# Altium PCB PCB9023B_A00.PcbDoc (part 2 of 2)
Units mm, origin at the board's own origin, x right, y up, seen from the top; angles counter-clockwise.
Board outline 30 x 45 mm, 4 copper layers (Top Layer, Signal Layer 2, Signal Layer 3, Bottom Layer), stack 1.606 mm thick; 75 components, 84 nets, 313 pads, 395 vias.
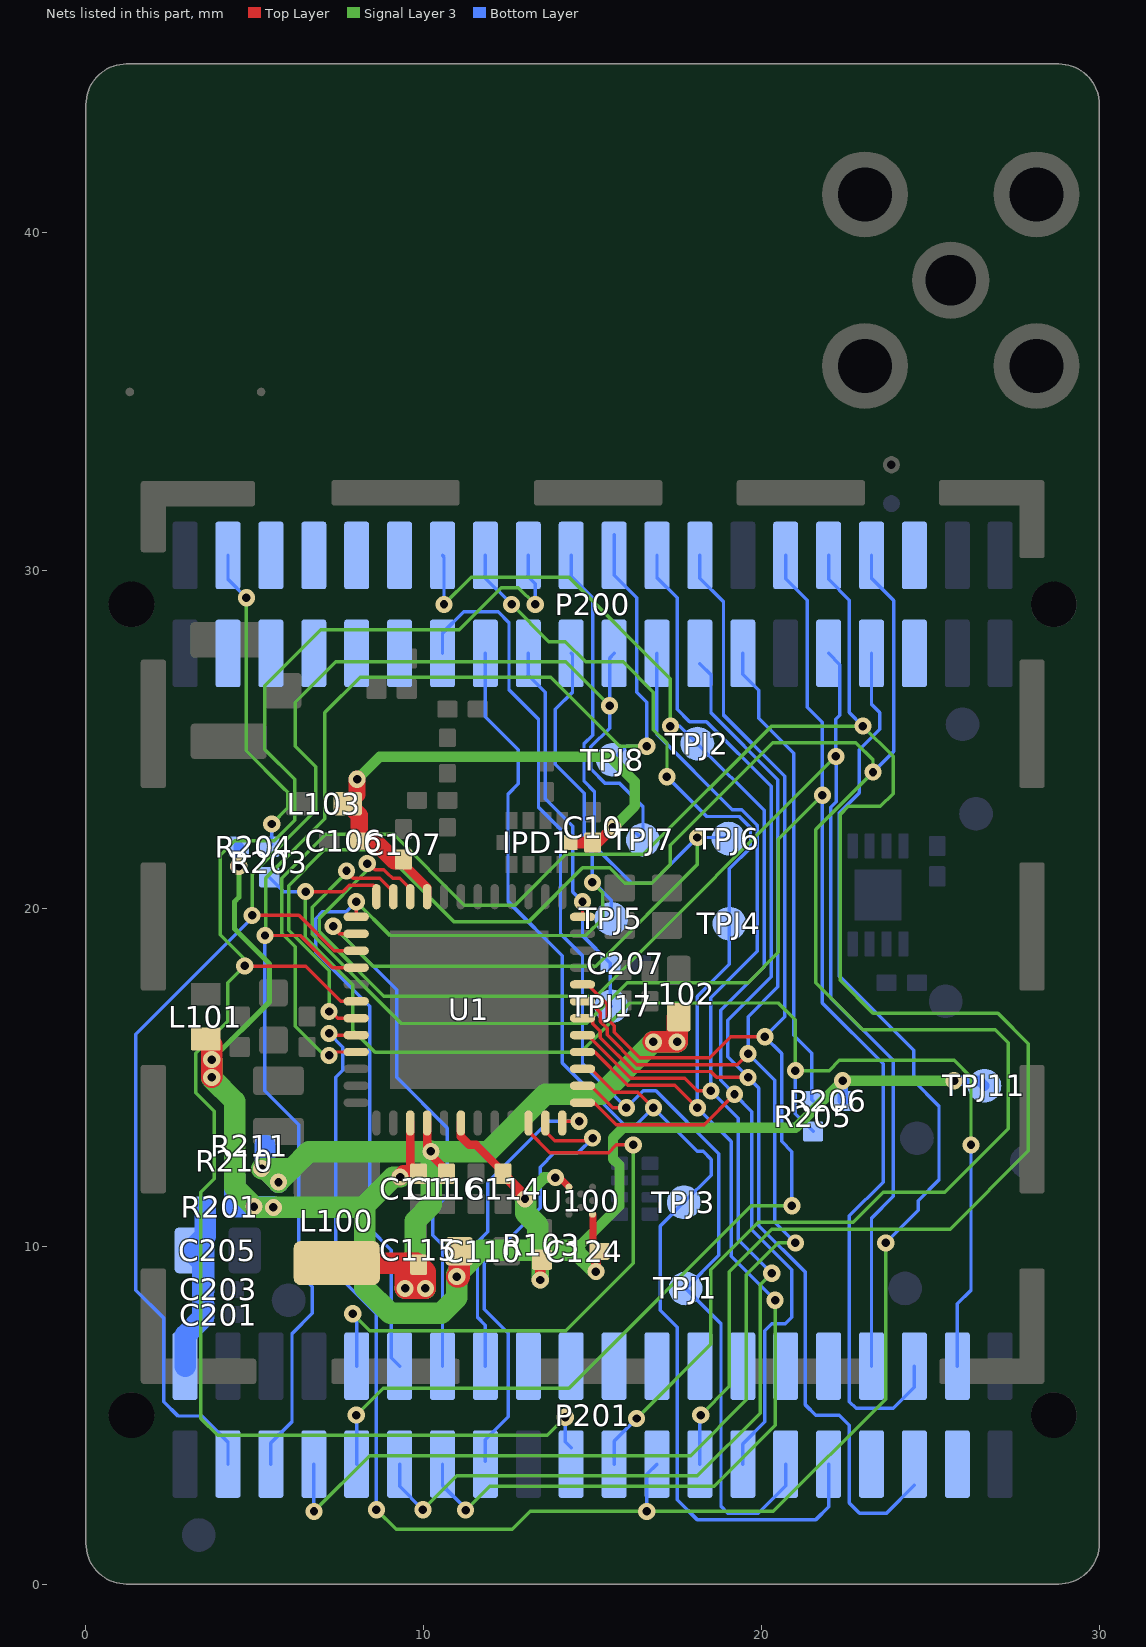
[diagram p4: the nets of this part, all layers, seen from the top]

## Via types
v1: diameter 0.508, hole 0.25, Top Layer to Bottom Layer, tented both sides, 364 vias
v2: diameter 0.5, hole 0.25, Top Layer to Bottom Layer, tented both sides, 31 vias

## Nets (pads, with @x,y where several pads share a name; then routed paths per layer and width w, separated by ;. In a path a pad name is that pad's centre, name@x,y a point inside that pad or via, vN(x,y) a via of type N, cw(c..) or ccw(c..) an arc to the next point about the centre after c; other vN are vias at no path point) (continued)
RADIO_#RESET: C207.1 P200.17 TPJ17.1 U1.12 | length 11.9
  Top Layer w0.102: U1.12@14.7,19.75 v1(14.7,20.2)
  Bottom Layer w0.102: P200.17@13.095,27.55 13.095,26.905 13.6,26.4 13.6,23.246 14.413,22.433 14.413,20.487 v1(14.7,20.2) 14.7,19.2 C207.1@15.525,18.375 15.525,17.125 TPJ17.1@15.55,17.1
RADIO_PA0: P200.19 P201.12 TPJ5.1 U1.25 | length 34
  Top Layer w0.102: U1.25@8,19.75 v1(8,20.2)
  Signal Layer 3 w0.102: v1(8,20.2) 9,19.2 14.8,19.2 15.3,19.7 15.3,20.464 v1(14.994,20.77)
  Bottom Layer w0.102: v1(8,20.2) 7.7,19.9 7,19.9 6.8,19.7 6.8,18.7 8.4,17.1 8.4,10.525 9.042,9.884 9.042,6.693 P201.12@9.285,6.45 ; P200.19@14.365,27.55 14.403,27.512 14.403,26.403 13.894,25.894 13.894,24.271 14.75,23.414 14.75,21.863 14.994,21.618 v1(14.994,20.77) 15.025,20.77 15.55,20.244 TPJ5.1@15.55,19.7
RADIO_PA1: P200.20 P201.14 TPJ6.1 U1.26 | length 42.9
  Top Layer w0.102: v1(7.32,19.472) 7.32,19.428 7.498,19.25 U1.26@8,19.25
  Signal Layer 3 w0.102: v1(7.32,19.472) 8.498,18.294 15.094,18.294 18.1,21.3 v1(18.1,22.1)
  Bottom Layer w0.102: v1(7.32,19.472) 9.2,17.592 9.2,15 10.7,13.5 10.7,11.5 10.269,11.069 10.269,10.331 10.555,10.045 P201.14@10.555,6.45 ; P200.20@14.365,30.45 14.365,29.835 15,29.2 15,25.125 14.744,24.87 14.744,23.769 ; 14.745,23.769 15.055,23.459 15.055,21.845 16.155,20.745 16.745,20.745 v1(18.1,22.1) 18.99,22.1 TPJ6.1@19.02,22.07
RADIO_PA2: P200.21 P201.3 TPJ7.1 U1.27 | length 47.4
  Top Layer w0.102: v1(4.919,19.794) 6.306,19.794 7.35,18.75 U1.27@8,18.75
  Signal Layer 3 w0.102: v1(4.919,19.794) 4.919,21.019 6.803,22.903 6.803,24.197 6.2,24.8 6.2,26.1 7.4,27.3 14.2,27.3 v1(15.5,26)
  Bottom Layer w0.102: P201.3@4.205,3.55 4.205,4.195 3.425,4.975 2.725,4.975 2.3,5.4 2.3,7.875 1.475,8.7 1.475,16.275 4.919,19.719 v1(4.919,19.794) ; P200.21@15.635,27.55 15.5,27.415 v1(15.5,26) 15.5,25.338 14.948,24.785 14.948,24.13 15.377,23.7 15.8,23.7 16.49,23.01 TPJ7.1@16.49,22.03 TPJ7.1@16.252,22.268
RADIO_PA3: P200.22 P201.5 TPJ8.1 U1.28 | length 45.8
  Top Layer w0.102: v1(5.3,19.2) 6.348,19.2 7.298,18.25 U1.28@8,18.25
  Signal Layer 3 w0.102: v1(5.3,19.2) 5.325,19.225 5.325,20.9 7.075,22.65 7.075,25.8 8.122,26.847 13.753,26.847 15.8,24.8 v1(16.6,24.8)
  Bottom Layer w0.102: v1(5.3,19.2) 5.294,19.194 5.294,14.606 6.3,13.6 6.3,9.2 6.7,8.8 6.7,8.016 6.1,7.416 6.1,4.8 5.475,4.175 P201.5@5.475,3.55 ; TPJ8.1@15.6,24.4 16,24.8 v1(16.6,24.8) 16.6,26.1 16.3,26.4 16.3,29.2 15.635,29.865 P200.22@15.635,30.45 P200.22@15.635,31.065
RADIO_PA5: P200.18 P201.19 U1.30 | length 51.8
  Top Layer w0.102: v1(4.7,18.3) 4.706,18.294 6.504,18.294 7.548,17.25 U1.30@8,17.25
  Signal Layer 3 w0.102: v1(13.3,29) 12.8,29.5 12.3,29.5 11.048,28.248 6.948,28.248 5.294,26.594 5.294,24.706 6.181,23.819 6.181,22.606 5.575,22 4.4,22 3.973,21.573 3.973,19.227 4.7,18.5 v1(4.7,18.3) 4.2,17.8 4.2,16.665 3.255,15.72 3.255,14.545 3.8,14 3.8,12 3.4,11.6 3.4,4.9 3.9,4.4 13.65,4.4 v1(14.188,4.938)
  Bottom Layer w0.102: P200.18@13.095,30.45 13.095,29.822 13.3,29.617 v1(13.3,29) ; v1(14.188,4.938) 14.188,4.215 P201.19@14.365,4.038
RADIO_PB11: P200.34 P201.21 U1.31 | length 67.5
  Top Layer w0.102: v1(7.198,16.95) 7.248,16.95 7.448,16.75 U1.31@8,16.75
  Signal Layer 3 w0.102: v1(7.198,16.95) 7.198,18.157 6,19.355 6,20.676 7.059,21.735 8.765,21.735 10.9,19.6 13.1,19.6 14.7,21.2 15.5,21.2 15.956,20.744 16.744,20.744 17.3,21.3 17.3,21.875 20.332,24.907 22.793,24.907 23.3,24.4 v1(23.3,24.037) 21.6,22.337 21.6,17.8 22.994,16.406 26.918,16.406 27.3,16.025 27.3,13.475 25.422,11.597 23.597,11.597 22.71,10.71 19.9,10.71 18.5,9.31 18.5,7.1 v1(16.3,4.9)
  Bottom Layer w0.102: P201.21@15.635,3.55 15.635,4.235 v1(16.3,4.9) ; P200.34@23.255,30.45 23.255,29.771 23.91,29.116 23.91,24.647 v1(23.3,24.037)
RADIO_PB12: P200.33 P201.23 U1.32 | length 58.7
  Top Layer w0.102: v1(7.198,16.3) 7.248,16.25 U1.32@8,16.25
  Signal Layer 3 w0.102: v1(8.6,2.2) 9.183,1.617 12.617,1.617 13.15,2.15 v1(16.6,2.15) 20.35,2.15 23.675,5.475 v1(23.675,10.1)
  Bottom Layer w0.102: v1(7.198,16.3) 7.604,15.894 7.604,15.204 7.4,15 7.4,9.2 8.6,8 v1(8.6,2.2) ; v1(16.6,2.15) 16.6,3.245 P201.23@16.905,3.55 ; P200.33@23.255,27.55 23.255,26.045 23.5,25.8 23.5,25.3 22.894,24.694 22.894,23.418 22.294,22.818 22.294,18.006 24.5,15.8 24.5,14.9 25.252,14.148 25.252,11.965 24.64,11.353 24.64,11.066 v1(23.675,10.1)
RADIO_PB13: P200.32 P201.25 U1.33 | length 68.2
  Top Layer w0.102: v1(7.198,15.65) 7.198,15.7 7.148,15.75 U1.33@8,15.75
  Signal Layer 3 w0.102: v1(7.198,15.65) 7.05,15.65 6.193,16.507 6.193,17.568 6.2,17.575 6.2,18.867 5.796,19.27 5.796,20.89 7.1,22.193 9.107,22.193 11.2,20.1 12.7,20.1 14.2,21.6 16.5,21.6 20.3,25.4 v1(23,25.4) 23.9,24.5 23.9,23.4 23.519,23.019 22.57,23.019 22.332,22.781 22.332,17.868 23.3,16.9 27,16.9 27.9,16 27.9,12.825 25.581,10.506 20.306,10.506 19.05,9.25 19.05,5.85 v1(18.2,5)
  Bottom Layer w0.102: P201.25@18.175,3.55 18.175,4.975 v1(18.2,5) ; P200.32@21.985,30.45 21.985,29.741 22.6,29.126 22.6,25.8 v1(23,25.4)
RADIO_PC9: P201.10 U1.46 | length 18.1
  Top Layer w0.102: U1.46@13.1,13.65 13.1,13.4 13.729,12.771 15.471,12.771 15.7,13 v1(16.2,13)
  Signal Layer 3 w0.102: v1(7.9,8) 8.4,7.5 14.2,7.5 16.2,9.5 v1(16.2,13)
  Bottom Layer w0.102: v1(7.9,8) 8.015,7.885 P201.10@8.015,6.45
RADIO_PC10: P201.15 U1.47 | length 13.7
  Top Layer w0.102: U1.47@13.6,13.65 13.6,13.4 13.877,13.123 14.923,13.123 v1(15,13.2)
  Bottom Layer w0.102: P201.15@11.825,3.635 11.825,4.275 12.5,4.95 12.5,7.425 11.794,8.131 11.794,9.494 13.444,11.144 13.444,12.344 13.866,12.766 14.566,12.766 v1(15,13.2)
RADIO_PC11: P201.16 U1.48 | length 9.6
  Top Layer w0.102: U1.48@14.098,13.65 U1.48@14.1,13.65 14.15,13.7 v1(14.6,13.7)
  Bottom Layer w0.102: P201.16@11.825,6.45 11.825,7.665 11.59,7.9 11.59,10.115 11.9,10.425 11.9,11.9 13.7,13.7 v1(14.6,13.7)
RADIO_PD13: P200.31 P201.34 U1.22 | length 45.8
  Top Layer w0.102: v1(8.325,21.328) 8.37,21.328 8.557,21.142 8.821,21.142 8.919,21.043 8.925,21.043 9.079,20.89 9.286,20.89 9.598,20.578 U1.22@9.598,20.35
  Signal Layer 3 w0.102: v1(8.325,21.328) 8.325,21.125 6.913,19.713 6.913,19.304 8.811,17.406 15.106,17.406 v1(22.2,24.5)
  Bottom Layer w0.102: P200.31@21.985,27.55 22.319,27.216 22.319,25.725 22.2,25.606 v1(22.2,24.5) 22.2,24.4 22.207,24.393 22.207,23.157 22.05,23 22.05,17.35 23.9,15.5 23.9,11.475 23.255,10.83 P201.34@23.255,6.45
RADIO_PD14: P200.30 P201.36 U1.23 | length 54.6
  Top Layer w0.102: v1(7.713,21.113) 7.713,21.087 7.906,20.894 8.698,20.894 9.1,20.493 U1.23@9.1,20.35
  Signal Layer 3 w0.102: v1(7.713,21.113) 7.713,21.053 6.697,20.036 6.697,19.233 9.336,16.594 14.814,16.594 16.021,17.8 19.6,17.8 20.5,18.7 20.5,22.05 v1(21.8,23.35)
  Bottom Layer w0.102: P200.30@20.715,30.45 20.715,29.761 21.35,29.126 21.35,25.95 21.794,25.506 21.794,24.332 21.8,24.325 v1(21.8,23.35) 21.8,17.2 23.6,15.4 23.6,11.9 22.6,10.9 22.6,5.4 22.8,5.2 23.9,5.2 24.525,5.825 P201.36@24.525,6.45
RADIO_PD15: P201.38 R203.1 R205.1 U1.24 | length 40.4
  Top Layer w0.102: v1(6.5,20.5) 7.609,20.5 7.8,20.691 8.509,20.691 8.6,20.6 U1.24@8.6,20.35
  Signal Layer 3 w0.102: v1(6.5,20.5) 6.494,20.494 6.494,19.149 7.9,17.742 7.9,16.4 8.556,15.744 14.644,15.744 16.1,17.2 20.5,17.2 21,16.7 v1(21,15.2) 22,15.2 22.3,15.5 25.7,15.5 26.2,15 v1(26.2,13)
  Bottom Layer w0.102: R203.1@5.425,20.925 5.85,20.5 v1(6.5,20.5) ; v1(21,15.2) 21,13.925 R205.1@21.525,13.4 ; P201.38@25.795,6.45 25.795,8.295 26.2,8.7 v1(26.2,13)
RADIO_PF0: P200.14 P201.27 TPJ2.1 U1.1 | length 41.7
  Top Layer w0.102: U1.1@14.7,14.25 14.998,14.25 15.024,14.224 15.076,14.224 15.7,13.6 18.3,13.6 v1(19.2,14.5)
  Signal Layer 3 w0.102: v1(10.6,29) 11.4,29.8 14.3,29.8 17.3,26.8 v1(17.3,25.4)
  Bottom Layer w0.102: P200.14@10.555,30.45 10.6,30.405 v1(10.6,29) ; v1(17.3,25.4) 17.58,25.4 TPJ2.1@18.1,24.88 20.079,22.901 20.079,18.279 18.79,16.99 18.79,14.91 v1(19.2,14.5) 19.713,13.987 19.713,10.487 20.9,9.3 20.9,7.9 20.7,7.7 20.3,7.7 20.1,7.5 20.1,4.8 19.445,4.145 P201.27@19.445,3.55
RADIO_PF1: P200.13 P201.29 TPJ1.1 U1.2 | length 38.3
  Top Layer w0.102: U1.2@14.7,14.75 14.948,14.75 15.598,14.1 v1(16,14.1)
  Bottom Layer w0.102: P200.13@10.555,27.55 10.555,28.155 11.182,28.782 12.204,28.782 12.524,28.461 12.524,26.476 13.397,25.603 13.397,22.993 14.048,22.341 14.048,19.252 14.7,18.6 14.7,15.4 v1(16,14.1) 16.5,14.6 16.875,14.6 18.738,12.736 18.738,9.738 TPJ1.1@17.75,8.75 18.8,7.7 18.8,2.3 19,2.1 19.9,2.1 20.715,2.915 P201.29@20.715,3.55
RADIO_PF2: P200.15 P201.31 TPJ3.1 U1.3 | length 39
  Top Layer w0.102: U1.3@14.7,15.25 14.948,15.25 15.634,14.564 16.336,14.564 v1(16.8,14.1)
  Bottom Layer w0.102: P200.15@11.825,27.55 11.825,25.675 12.8,24.7 12.8,23.687 12.494,23.381 12.494,20.206 14.1,18.6 14.1,15.425 15.932,13.594 16.294,13.594 v1(16.8,14.1) 18.094,12.806 18.268,12.806 18.506,12.568 18.506,12.106 TPJ3.1@17.7,11.3 17,10.6 17,8.1 17.5,7.6 17.5,2.5 18.103,1.897 21.597,1.897 21.985,2.285 P201.31@21.985,3.55
RADIO_PF3: P200.16 P201.13 TPJ4.1 U1.4 | length 48
  Top Layer w0.102: U1.4@14.7,15.75 15.062,15.75 16.045,14.767 17.433,14.767 v1(18.1,14.1)
  Signal Layer 3 w0.102: v1(11.238,2.188) 11.95,2.9 18.6,2.9 20.4,4.7 v1(20.4,8.4) ; v1(12.6,29) 13.7,27.9 14.19,27.9 14.79,27.3 15.9,27.3 16.8,26.4 16.8,25.3 16.795,25.295 17.2,24.89 v1(17.2,23.9)
  Bottom Layer w0.102: P201.13@10.555,3.55 10.555,2.918 11.238,2.235 v1(11.238,2.188) ; P200.16@11.825,30.45 11.825,29.775 v1(12.6,29) ; v1(17.2,23.9) 18.378,22.722 19.335,22.722 19.672,22.385 19.672,21.8 19.05,21.177 TPJ4.1@19.05,19.55 19.05,18.35 18.094,17.394 18.094,14.106 v1(18.1,14.1) 19.1,13.1 19.1,9.7 v1(20.4,8.4)
RADIO_PF4: P200.23 P201.11 U1.5 | length 42.6
  Top Layer w0.102: U1.5@14.698,16.25 U1.5@14.7,16.25 14.85,16.25 16.13,14.971 17.729,14.971 18.1,14.6 v1(18.5,14.6)
  Signal Layer 3 w0.102: v1(9.975,2.2) 10.975,3.2 18.1,3.2 19.957,5.057 19.957,8.857 v1(20.3,9.2)
  Bottom Layer w0.102: P201.11@9.285,3.55 9.285,2.89 v1(9.975,2.2) ; P200.23@16.905,27.55 16.894,27.539 16.894,25.164 19.132,22.926 19.419,22.926 19.876,22.469 19.876,18.738 18.5,17.362 v1(18.5,14.6) 19.306,13.794 19.306,10.194 v1(20.3,9.2)
RADIO_PF5: P200.24 P201.35 U1.6 | length 40.3
  Top Layer w0.102: U1.6@14.8,16.8 14.9,16.8 15,16.7 15,16.592 15.227,16.365 15.227,16.173 16.226,15.174 18.5,15.174 18.667,15.006 19.594,15.006 v1(19.6,15)
  Bottom Layer w0.102: P200.24@16.905,30.45 16.905,29.795 17.5,29.2 17.5,25.9 17.868,25.532 18.37,25.532 20.282,23.621 20.282,17.982 18.994,16.694 18.994,15.606 v1(19.6,15) 19.916,14.684 19.916,10.609 21.3,9.225 21.3,5.3 21.603,4.997 22.303,4.997 22.6,4.7 22.6,2.4 22.9,2.1 23.7,2.1 P201.35@24.525,2.925
RADIO_PF6: P200.25 P201.7 U1.7 | length 46.2
  Top Layer w0.102: U1.7@14.698,17.25 U1.7@14.7,17.25 14.898,17.25 15.227,16.921 15.227,16.652 15.431,16.449 15.431,16.257 16.31,15.377 19.277,15.377 v1(19.6,15.7)
  Signal Layer 3 w0.102: v1(6.75,2.15) 8.4,3.8 17.9,3.8 19.55,5.45 19.55,9.15 20.5,10.1 v1(21,10.1)
  Bottom Layer w0.102: v1@6.745,2.155 P201.7@6.745,3.55 ; P200.25@18.175,27.25 18.503,26.922 18.503,25.797 20.485,23.815 20.485,17.685 19.6,16.8 v1(19.6,15.7) 20.39,14.91 20.39,10.71 v1(21,10.1)
RADIO_PF7: P200.26 P201.9 U1.8 | length 44.7
  Top Layer w0.102: U1.8@14.7,17.75 14.842,17.75 15.431,17.162 15.431,16.736 15.634,16.533 15.634,16.341 16.395,15.58 18.467,15.58 19.087,16.2 v1(20.1,16.2)
  Signal Layer 3 w0.102: v1(8,5) 8.8,5.8 14.3,5.8 19.7,11.2 v1(20.9,11.2)
  Bottom Layer w0.102: v1(8,5) 8.006,5 8.015,4.991 P201.9@8.015,3.55 ; P200.26@18.175,30.45 18.175,29.776 18.874,29.077 18.874,25.726 20.688,23.912 20.688,16.788 v1(20.1,16.2) 20.594,15.706 20.594,13.106 20.9,12.8 v1(20.9,11.2)
USB_VBUS: P200.35
USB_VREG: P200.36
VBIAS: C10.1 C106.1 C107.1 IPD1.10 L103.2 U1.21 | length 16.8
  Top Layer w0.254: C107.1@9.386,21.337 10.098,20.625 U1.21@10.098,20.35
  Top Layer w0.305: C10.1@15,21.95 15.15,21.95 v1(15.6,22.4)
  Top Layer w0.356: IPD1.10@14.35,21.95 C10.1@15,21.95
  Top Layer w0.508: v1(8.025,23.825) 8.025,23.375 L103.2@7.75,23.1 8.09,22.76 8.09,22.01 C106.1@8.1,22 8.538,22 9.138,21.4 C107.1@9.4,21.4
  Signal Layer 3 w0.305: v1(8.025,23.825) 8.692,24.492 15.508,24.492 16.25,23.75 16.25,23.032 15.618,22.4 v1(15.6,22.4)
VDCDC: C115.1 C116.1 L100.2 L102.1 R211.2 U1.40 | length 29.6
  Top Layer w0.254: U1.40@10.098,13.65 v1@10.098,12.821 ; v1(10.21,12.806) 10.194,12.821 v1@10.098,12.821 ; C116.1@10.675,12.15 10.675,12.244 v1@10.098,12.821
  Top Layer w0.635: L100.2@7.398,9.5 C115.1@9.798,9.5 ; v1(16.8,16.05) v1(17.5,16.05) L102.1@17.5,16.775 ; C115.1@9.798,9.5 9.448,9.15 v1(9.448,8.75) v1(10.048,8.75) 10.048,9.25 C115.1@9.798,9.5
  Signal Layer 3 w0.635: v1(5.2,12.3) v1@5.3,12.3 ; v1@10.003,8.795 9.748,9.05 ; v1(10.048,8.75) v1(9.448,8.75) 9.748,9.05 ; v1@10.225,12.806 v1@10.225,12.8 ; v1(17.5,16.05) v1(16.8,16.05) 15.25,14.5 13.6,14.5 11.9,12.8 v1@10.225,12.8 ; v1@5.3,12.3 v1(5.7,11.9) 6.1,12.3 ; v1@5.3,12.3 6.1,12.3 ; 6.1,12.3 6.6,12.8 v1@10.225,12.8 ; 9.748,9.05 9.748,10.748 10.225,11.225 v1@10.225,12.8
  Bottom Layer w0.635: R211.2@5.3,12.975 5.3,12.3 v1(5.7,11.9)
VMCU: C110.1 C111.1 C114.1 C124.1 L101.1 R103.1 R201.2 R204.1 R206.1 R210.2 TPJ11.1 U1.39 U1.42 U100.A1 U100.E3 | length 60.6
  Top Layer w0.203: v1(13.898,12.034) 14.014,12.034 U100.E3@14.298,11.75 ; U100.A1@14.998,10.95 15.01,10.938 15.01,9.938 C124.1@15.098,9.85
  Top Layer w0.254: U1.39@9.598,13.65 9.598,12.4 C111.1@9.848,12.15 ; U1.42@11.098,13.65 11.098,13.25 11.348,13 11.548,13 C114.1@12.348,12.2
  Top Layer w0.305: C114.1@12.348,12.2 12.392,12.156 12.392,12.09 12.69,11.792 12.69,11.79 12.854,11.626 12.854,11.544 v1(12.998,11.4) ; v1(13.45,9) 13.45,9.55 R103.1@13.5,9.6 ; v1(15.098,9.25) C124.1@15.098,9.85
  Top Layer w0.508: v1(9.298,12.05) 9.398,12.15 C111.1@9.848,12.15
  Top Layer w0.635: L101.1@3.55,16.135 3.725,15.96 v1(3.725,15.525) v1(3.725,15) ; v1(10.976,9.1) 11.05,9.1 C110.1@11.05,9.85
  Signal Layer 3 w0.15: v1(3.725,15.525) 5.431,17.231 5.431,18.36 4.394,19.397 4.394,20.2 4.525,20.331 v1(4.525,21.25)
  Signal Layer 3 w0.305: 13.4,9.875 13.45,9.825 ; 14.473,9.875 15.795,11.197 15.795,12.395 15.6,12.59 15.6,13.2 15.908,13.508 21.008,13.508 v1(22.4,14.9) 25.65,14.9 25.675,14.875 v1(25.7,14.9)
  Signal Layer 3 w0.33: v1(12.998,11.4) 12.998,11.464 13.568,12.034 v1(13.898,12.034)
  Signal Layer 3 w0.508: v1(13.45,9) 13.45,9.825 ; 14.473,9.875 v1(15.098,9.25)
  Signal Layer 3 w0.635: v1(3.725,15.525) v1(3.725,15) 3.725,14.973 4.4,14.298 4.4,11.75 v1(4.975,11.175) 5,11.15 v1(5.55,11.15) 8.196,11.15 8.248,11.202 ; v1(9.298,12.05) 9.096,12.05 8.248,11.202 ; v1(12.998,11.4) 13.021,11.377 13.021,10.977 13.375,10.623 13.375,10.221 13.4,10.196 13.4,9.875 ; 14.473,9.875 13.4,9.875 ; 8.248,11.202 8.248,8.775 9.01,8.013 10.513,8.013 10.976,8.476 v1(10.976,9.1) 10.976,9.176 11.675,9.875 13.4,9.875
  Bottom Layer w0.305: v1(4.525,21.25) R204.1@4.525,21.825 ; v1(22.4,14.9) 22.4,14.325 R206.1@22.425,14.3 ; v1(25.7,14.9) 26.45,14.9 TPJ11.1@26.6,14.75
  Bottom Layer w0.635: R210.2@4.4,12.075 4.4,11.2 R201.2@4.425,11.175 v1(4.975,11.175) ; v1@5.073,11.175 v1(4.975,11.175) ; v1(5.55,11.15) 5.537,11.163 4.975,11.163 v1(4.975,11.175)
VMCU_IN: C201.1 C203.1 C205.1 P201.2 R201.1 | length 7.3
  Bottom Layer w0.635: P201.2@2.935,6.45 2.935,7.36 C201.1@3.488,7.913 ; 3.488,8.275 C201.1@3.488,7.913 ; C205.1@3.5,10.25 3.488,10.238 3.488,8.688 C203.1@3.463,8.663 ; R201.1@3.525,11.175 3.525,10.3 C205.1@3.1,9.875 3.463,9.512 C203.1@3.463,8.663 ; C203.1@3.463,8.663 3.463,7.938 C201.1@3.488,7.913
WSTK_F14: P200.27 R205.2 R206.2 | length 14.1
  Bottom Layer w0.102: P200.27@19.445,27.55 19.445,26.93 19.92,26.455 19.92,25.63 20.95,24.6 20.95,16.25 21.49,15.71 21.49,14.335 R205.2@21.525,14.3
WSTK_P15: P201.18
WSTK_P17: P201.20
WSTK_P19: P201.22
WSTK_P21: P201.24
WSTK_P23: P201.26
WSTK_P25: P201.28
WSTK_P27: P201.30
WSTK_P29: P201.32
WSTK_P30: P201.33
WSTK_P34: P201.37
WSTK_P36: P200.3
WSTK_P37: P200.4 R203.2 R204.2 | length 9.7
  Signal Layer 3 w0.102: v1(4.75,29.2) 4.75,24.663 5.834,23.579 5.977,23.435 5.977,22.977 v1(5.5,22.5)
  Bottom Layer w0.102: P200.4@4.205,30.45 4.205,29.745 v1(4.75,29.2) ; R204.2@5.425,21.825 5.5,21.9 5.4,22 5.5,22.1 v1(5.5,22.5)
WSTK_P38: P200.5
WSTK_P39: P200.6
WSTK_P40: P200.7
WSTK_P41: P200.8
WSTK_P42: P200.9
WSTK_P43: P200.10
WSTK_P44: P200.11
WSTK_P45: P200.12
pads on no net: P200.M1 P200.M2 P201.40 P201.M1 P201.M2 RP200.4 RP200.5 TPJ9.1 TPJ18.1 TPJ19.1 TPJ20.1 U1.49@10.2,15.85 U1.49@10.2,18.15 U1.49@12.5,15.85 U1.49@12.5,18.15 U100.C1 U200.9

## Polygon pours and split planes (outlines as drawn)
GND on Top Layer "GND_L1" (solid, remove dead copper, pour order 29): 0.605,34.64 20.99,34.64 ccw(c20.99,35.507) 21.857,35.507 21.857,40.54 23.657,42.34 27.557,42.34 29.357,40.54 29.355,1.155 cw(c28.79,1.155) 28.79,0.59 1.255,0.595 cw(c1.255,1.245) 0.605,1.245
GND on Signal Layer 2 "GND_L2" (solid, remove dead copper, pour order 27): 0.605,34.64 20.99,34.64 ccw(c20.99,35.507) 21.857,35.507 21.857,40.54 23.657,42.34 27.557,42.34 29.357,40.54 29.355,1.155 cw(c28.79,1.155) 28.79,0.59 1.255,0.595 cw(c1.255,1.245) 0.605,1.245
GND on Signal Layer 3 "GND_L3" (solid, remove dead copper, pour order 25): 0.605,34.64 20.99,34.64 ccw(c20.99,35.507) 21.857,35.507 21.857,40.54 23.657,42.34 27.557,42.34 29.357,40.54 29.355,1.155 cw(c28.79,1.155) 28.79,0.59 1.255,0.595 cw(c1.255,1.245) 0.605,1.245
GND on Bottom Layer "GND_L4" (solid, remove dead copper, pour order 24): 0.605,34.64 20.99,34.64 ccw(c20.99,35.507) 21.857,35.507 21.857,40.54 23.657,42.34 27.557,42.34 29.357,40.54 29.355,1.155 cw(c28.79,1.155) 28.79,0.59 1.255,0.595 cw(c1.255,1.245) 0.605,1.245

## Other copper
Top Layer:
  pour cut-out: 13.1,24.1 14.1,24.1 14.1,22.9 14,23 13.1,23
  pour cut-out: 8.5,19.8 10.2,19.8 10.2,20.4 8.4,22.2 8.4,23 11.2,23 11.2,19.8 14.2,19.8 14.2,14.2 8.5,14.2
Signal Layer 2:
  pour cut-out: 3.047,27.306 3.047,25.606 5.129,25.606 5.129,25.874 6.425,25.875 6.425,27.044 5.13,27.044 5.13,27.305
Bottom Layer:
  pour cut-out: 23.845,33.935 cw(c23.845,33.135) 24.645,33.135 cw(c23.845,33.135) 23.845,32.335 cw(c23.845,33.135) 23.045,33.135 cw(c23.845,33.135)

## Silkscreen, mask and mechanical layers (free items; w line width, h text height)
Top Overlay:
  text "EFR32 IPD" at 1,41.4 h3.85
  text "2.4 GHz" at 0.7,39 h1.9
  text "434 MHz" at 13.5,39 h1.9
  text "10 dBm" at 0.7,37 h1.9
  text "10 dBm" at 13.5,37 h1.9
  text "EFR32xG1x" at 10.5,7.5 h1.9
Bottom Overlay:
  lines w0.152: 3.95,11.925 3.95,11.625 4.25,11.625 ; 3.95,13.175 3.95,13.475 4.25,13.475 ; 4.075,21.65 4.075,21.35 4.375,21.35 ; 4.075,22 4.075,22.3 4.375,22.3 ; 4.6,11.625 4.9,11.625 4.9,11.925 ; 4.625,21.35 4.925,21.35 4.925,21.05 ; 4.9,12.175 4.9,12.475 5.2,12.475 ; 4.925,20.75 4.925,20.425 5.225,20.425 ; 5.5,12.475 5.825,12.475 5.825,12.775 ; 5.5,13.475 5.825,13.475 5.825,13.175 ; 5.625,20.425 5.925,20.425 5.925,20.75 ; 5.625,22.3 5.925,22.3 5.925,22 ; 21.075,13.25 21.075,12.95 21.375,12.95 ; 21.075,14.5 21.075,14.8 21.375,14.8 ; 21.725,12.95 22.025,12.95 22.025,13.25 ; 22.025,13.5 22.025,13.8 22.325,13.8 ; 22.625,13.8 22.95,13.8 22.95,14.1 ; 22.625,14.8 22.95,14.8 22.95,14.5
  text "BOARD INFO" at 20.55,43.35 h1.6
  text "Sensor Enable" at 9.55,22.825 h1.6
  text "ON" at 3.8,21.475 h1.2
  text "PD15" at 8.7,21.325 h1.2
  text "Disp Enable" at 25.275,15.125 h1.6
  text "ON" at 24.6,13.95 h1.2
  text "PAVDD" at 6.6,13.85 h1.6
  text "PCB9023B Rev. A00" at 27.625,13.725 h1.52 r270
  text "PD15" at 20.701,13.589 h1.2
  text "VDCDC" at 9.6,12.6 h1.2
  text "VMCU" at 3.7,12.3 h1.2
Top Solder:
  the board outline again, w1
Bottom Solder:
  the board outline again, w1
BOARD OUTLINE 1:
  the board outline again, w0.1
Mechanical 11:
  the board outline again, w0.1
Mechanical 12:
  the board outline again, w0.1
EXT_SILKP 20:
  lines w0.152: 3.95,11.925 3.95,11.625 4.25,11.625 ; 3.95,13.175 3.95,13.475 4.25,13.475 ; 4.075,21.65 4.075,21.35 4.375,21.35 ; 4.075,22 4.075,22.3 4.375,22.3 ; 4.6,11.625 4.9,11.625 4.9,11.925 ; 4.625,21.35 4.925,21.35 4.925,21.05 ; 4.9,12.175 4.9,12.475 5.2,12.475 ; 4.925,20.75 4.925,20.425 5.225,20.425 ; 5.5,12.475 5.825,12.475 5.825,12.775 ; 5.5,13.475 5.825,13.475 5.825,13.175 ; 5.625,20.425 5.925,20.425 5.925,20.75 ; 5.625,22.3 5.925,22.3 5.925,22 ; 21.075,13.25 21.075,12.95 21.375,12.95 ; 21.075,14.5 21.075,14.8 21.375,14.8 ; 21.725,12.95 22.025,12.95 22.025,13.25 ; 22.025,13.5 22.025,13.8 22.325,13.8 ; 22.625,13.8 22.95,13.8 22.95,14.1 ; 22.625,14.8 22.95,14.8 22.95,14.5
  lines w0.154: 1.5,38 1.5,37 2.5,37 ; 1.5,42 1.5,43 2.5,43 ; 19.5,37 20.5,37 20.5,38 ; 19.5,43 20.5,43 20.5,42
  text "BOARD INFO" at 20.55,43.35 h1.52
  text "Sensor Enable" at 9.45,22.85 h1.52
  text "ON" at 3.8,21.475 h1.14
  text "WSTK_P37" at 11.475,21.025 h1.14
  text "Disp Enable" at 25.275,15.125 h1.52
  text "ON" at 24.6,13.95 h1.14
  text "PAVDD" at 6.85,13.9 h1.52
  text "WSTK_P35" at 20.95,13.475 h1.14
  text "VDCDC" at 9.6,12.6 h1.14
  text "VMCU" at 3.825,12.15 h1.14
Mechanical 26:
  lines w0.2: -125.405,-47.962 -120.405,-47.962 ; -125.405,-0.962 -120.405,-0.962 ; -125.393,46.038 -120.405,46.038 ; -54.197,-94.993 -54.197,-89.993 ; -54.197,90.007 -54.197,95.007 ; 17.103,-94.993 17.103,-89.993 ; 17.103,90.007 17.103,95.007 ; 88.303,-94.993 88.303,-89.993 ; 88.303,90.007 88.303,95.007 ; 154.595,-47.962 159.595,-47.962 ; 154.595,-0.962 159.595,-0.962 ; 154.595,46.038 159.583,46.038 ; -125.393,-94.993 -125.393,94.999 159.595,94.999 159.595,-94.993 -125.393,-94.993 ; -120.405,-89.993 -120.405,90.007 154.595,90.007 154.595,-89.993 -120.405,-89.993
  text "1" at -92.505,91.578 h1.52
  text "2" at -20.197,91.578 h1.52
  text "3" at 52.403,91.578 h1.52
  text "4" at 123.203,91.578 h1.52
  text "D" at 156.593,72.438 h1.52
  text "D" at -123.518,71.233 h1.52
  text "C" at -123.518,23.738 h1.52
  text "C" at 156.466,23.738 h1.52
  text "B" at -123.518,-23.862 h1.52
  text "B" at 156.466,-23.862 h1.52
  text "A" at -123.518,-71.362 h1.52
  text "A" at 156.466,-71.362 h1.52
  text "1" at -91.285,-93.435 h1.52
  text "2" at -20.197,-93.435 h1.52
  text "3" at 52.103,-93.435 h1.52
  text "4" at 122.803,-93.435 h1.52
Mechanical 27:
  circle w0.152: c70.608,-82.839 r1.778
  circle w0.152: c70.608,-82.839 r0.762
  lines w0.152: 59.609,-82.839 66.975,-82.839 ; 68.322,-82.839 72.894,-82.839 ; 60.371,-83.601 60.371,-82.077 66.213,-81.061 66.188,-84.617 60.371,-83.601
  lines w0.2: 34.575,-89.95 34.575,-77.425 ; 34.575,-77.369 74.589,-77.369 ; 34.589,-86.369 74.589,-86.369 ; 54.869,-86.322 54.869,-77.407 ; 134.589,-89.98 134.589,-86.369 ; 144.589,-86.369 144.589,-77.369 ; 154.589,-86.369 74.589,-86.369 ; 154.589,-77.369 74.589,-77.369 ; 74.589,-86.369 74.589,-77.369
  text "SIZE" at 36.589,-79.369 h1.52
  text "DOC NO" at 76.589,-79.369 h1.52
  text "REV" at 146.589,-79.369 h1.52
  text "PROJECTION" at 55.885,-79.718 h1.52
  text ".BoardRevision" at 146.309,-84.29 h2.54
  text "A4" at 39.239,-84.744 h2.54
  text ".BoardName" at 79.088,-84.744 h2.54
  text "REF" at 36.589,-88.369 h1.52
  text "SHEET" at 135.589,-88.369 h1.52
  text "1 of 2" at 145.43,-89.406 h1.52
Mechanical 28:
  lines w0.2: -125.404,-47.963 -120.404,-47.963 ; -125.404,-0.963 -120.404,-0.963 ; -125.392,46.037 -120.404,46.037 ; 154.596,-47.963 159.596,-47.963 ; 154.596,46.037 159.596,46.037
  lines w0.203: -120.429,-89.995 -120.429,90.005 ; -120.404,-89.995 154.596,-89.995 154.596,90.005 -120.404,90.005 ; -54.196,-94.995 -54.196,-89.995 ; -54.196,90.005 -54.196,95.005 ; 17.104,-94.995 17.104,-89.995 ; 17.104,90.005 17.104,95.005 ; 88.304,-94.995 88.304,-89.995 ; 88.304,90.005 88.304,95.005 ; -125.392,-94.995 -125.392,94.997 159.596,94.997 159.596,-94.995 -125.392,-94.995
  text "4" at -91.487,91.577 h1.52
  text "3" at -19.18,91.577 h1.52
  text "2" at 53.42,91.577 h1.52
  text "1" at 124.22,91.577 h1.52
  text "D" at 157.61,72.437 h1.52
  text "D" at -122.501,71.232 h1.52
  text "C" at -122.501,23.737 h1.52
  text "C" at 157.61,22.137 h1.52
  text "B" at -122.501,-23.863 h1.52
  text "B" at 157.61,-24.963 h1.52
  text "A" at 156.592,-71.287 h1.52
  text "A" at -122.501,-71.363 h1.52
  text "A" at 157.483,-71.363 h1.52
  text "4" at -90.268,-93.437 h1.52
  text "3" at -19.18,-93.437 h1.52
  text "2" at 52.967,-93.437 h1.52
  text "1" at 123.82,-93.437 h1.52
Mechanical 29:
  circle w0.152: c-36.426,-82.828 r1.778
  circle w0.152: c-36.426,-82.828 r0.762
  lines w0.152: -38.712,-82.828 -34.14,-82.828 ; -32.794,-82.828 -25.428,-82.828 ; -32.032,-81.05 -26.19,-82.066 -26.19,-83.59 -32.006,-84.606 -32.032,-81.05
  lines w0.2: -120.407,-86.359 -40.407,-86.359 ; -120.407,-77.359 -40.407,-77.359 ; -110.407,-86.359 -110.407,-77.359 ; -100.407,-89.969 -100.407,-86.359 ; -20.687,-86.311 -20.687,-77.396 ; -0.407,-86.359 -40.407,-86.359 ; -0.407,-77.359 -40.407,-77.359 ; -0.393,-89.518 -0.393,-77.4 ; -40.407,-86.359 -40.407,-77.359
  text "REV" at -112.407,-79.359 h1.52
  text "DOC NO" at -42.407,-79.359 h1.52
  text "SIZE" at -2.407,-79.359 h1.52
  text "PROJECTION" at -21.703,-79.707 h1.52
  text ".BoardRevision" at -111.952,-84.29 h2.54
  text ".BoardName" at -44.906,-84.733 h2.54
  text "A4" at -5.057,-84.733 h2.54
  text "SHEET" at -101.407,-88.359 h1.52
  text "REF" at -2.407,-88.359 h1.52
  text "2 of 2" at -111.095,-89.331 h1.52
Mechanical 30:
  lines w0.2: 34.575,-77.369 34.575,-56.53 154.575,-56.53 ; 34.575,-73.434 74.575,-73.434 ; 34.575,-69.434 74.575,-69.434 ; 34.575,-65.434 74.575,-65.434 ; 74.575,-69.435 154.575,-69.435 ; 74.575,-61.434 154.575,-61.434 ; 74.581,-77.369 74.581,-56.53 ; 74.581,-56.519 74.581,-47.925 154.625,-47.925
  text "BRD9023A: EFR32xG1x 2.4 GHz / 868 MHz 13 dBm IPD" at 75.675,-51.3 h1.6
  text "BRD9023B: EFR32xG1x 2.4 GHz / 434 MHz 10 dBm IPD" at 75.675,-54.575 h1.6
  text "CUSTOMER" at 75.683,-58.446 h1.27
  text "PROJECT NO" at 36.059,-59.462 h1.52
  text "SILICON LABS" at 93.125,-60.3 h2.5
  text "DRAWING TITLE" at 75.912,-63.374 h1.52
  text "BRD9023" at 36,-64.3 h2.1
  text "DATE" at 36.059,-67.59 h1.52
  text "EFR32xG1x QFN48 Dual-Band Radio Board with IPD" at 75.825,-67.625 h1.6
  text "'.Print_Date'" at 54.347,-68.606 h1.52
  text "SHEET NAME" at 75.709,-71.527 h1.52
  text "DRAWN" at 36.059,-71.654 h1.52
  text "CHECK" at 36.059,-75.718 h1.52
